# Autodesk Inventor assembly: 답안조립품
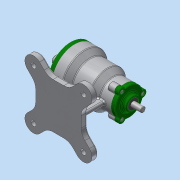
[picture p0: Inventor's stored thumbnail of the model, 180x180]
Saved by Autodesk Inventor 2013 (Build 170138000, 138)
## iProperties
Created: 2017-03
Part Number: 답안조립품
Document SubType Name: Assembly
Designer: Administrator
Author: Administrator
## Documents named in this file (12)
- C:\Users\Administrator\Desktop\470307V1004\답안조립품.iam
- C:\Users\Administrator\Desktop\470307V1004\본체.ipt
- C:\Users\Administrator\Desktop\470307V1004\뒤커버.ipt
- C:\Users\Administrator\Desktop\470307V1004\앞커버.ipt
- C:\Users\Administrator\Desktop\470307V1004\오일 실 10 20 7.ipt
- C:\Users\Administrator\Desktop\470307V1004\오일 실 17 30 8.ipt
- C:\Users\Administrator\Desktop\470307V1004\베어링-6200.ipt
- C:\Users\Administrator\Desktop\470307V1004\베어링-6203.ipt
- C:\Users\Administrator\Desktop\470307V1004\축.ipt
- C:\Users\Administrator\Desktop\470307V1004\키5x5.ipt
- C:\Users\Administrator\Desktop\470307V1004\스프로킷.ipt
- C:\Users\Administrator\Desktop\470307V1004\볼트 M4 x 12.ipt
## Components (9 placed, 1 different names)
1. ISO 4762 M4 x 12:1
2. ISO 4762 M4 x 12:3
3. ISO 4762 M4 x 12:4
4. ISO 4762 M4 x 12:5
5. ISO 4762 M4 x 12:6
6. ISO 4762 M4 x 12:7
7. ISO 4762 M4 x 12:2
8. ISO 4762 M4 x 12:8
9. ISO 4762 M4 x 12:9
